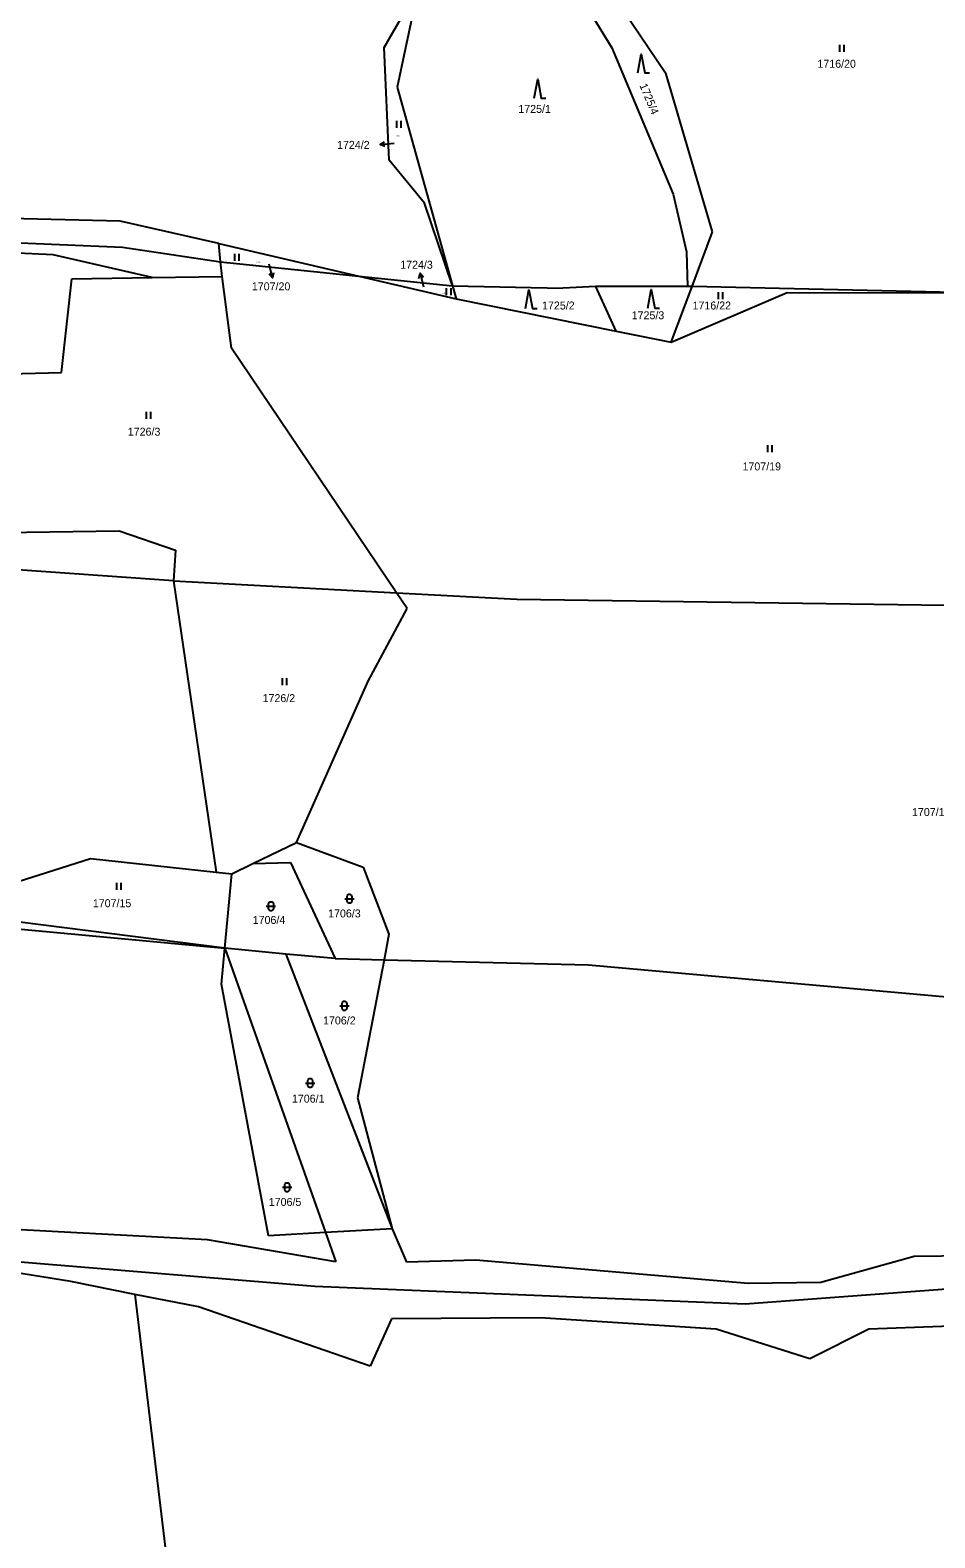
# Model space of a CAD drawing. Extents: x -609861 to -605046, y -1120287 to -1116307.
# Drawn here: x -608546.9 to -608353.7, y -1119519.3 to -1119197.4 of the extents above; entities that cross this region are included whole.
import ezdxf

# ---------------------------------------------------------------- set-up
doc = ezdxf.new("R2010")
doc.units = 0
for name, color, linetype in [('Vrstva 1', 7, 'Continuous'), ('Vrstva 2', 7, 'Continuous'), ('Vrstva 3', 7, 'Continuous'), ('Vrstva 7', 7, 'Continuous')]:
    doc.layers.add(name, color=color, linetype=linetype)

msp = doc.modelspace()

# ---------------------------------------------------------------- linework, layer by layer
at = {"layer": 'Vrstva 1'}
for p, q in [((-608446.56, -1119162.06), (-608422.64, -1119201.2)), ((-608411.09, -1119206.8), (-608441.64, -1119161.43)), ((-608471.27, -1119201.14), (-608463.96, -1119188.36)), ((-608463.96, -1119188.36), (-608468.52, -1119209.58)), ((-608470.2, -1119225.18), (-608471.27, -1119201.14)), ((-608422.64, -1119201.2), (-608409.54, -1119232.39)), ((-608401.21, -1119240.49), (-608411.09, -1119206.8)), ((-608468.52, -1119209.58), (-608456.66, -1119252)), ((-608462.69, -1119234.31), (-608470.2, -1119225.18)), ((-608409.54, -1119232.39), (-608406.75, -1119244.71)), ((-608527.65, -1119238.15), (-608582.05, -1119236.84)), ((-608456.66, -1119252), (-608462.69, -1119234.31)), ((-608617.51, -1119239.98), (-608527.15, -1119243.75)), ((-608506.57, -1119242.93), (-608527.65, -1119238.15)), ((-608506.18, -1119246.86), (-608506.57, -1119242.93)), ((-608506.57, -1119242.93), (-608476.7, -1119249.92)), ((-608405.54, -1119252.11), (-608401.21, -1119240.49)), ((-608541.93, -1119245.35), (-608572.44, -1119243.93)), ((-608520.83, -1119250.21), (-608541.93, -1119245.35)), ((-608527.15, -1119243.75), (-608506.18, -1119246.86)), ((-608406.75, -1119244.71), (-608406.51, -1119252.09)), ((-608520.83, -1119250.21), (-608505.87, -1119249.96)), ((-608506.18, -1119246.86), (-608476.7, -1119249.92)), ((-608505.87, -1119249.96), (-608506.18, -1119246.86)), ((-608503.85, -1119265.31), (-608505.87, -1119249.96)), ((-608476.7, -1119249.92), (-608456.66, -1119252)), ((-608476.7, -1119249.92), (-608455.88, -1119254.79)), ((-608540.17, -1119270.5), (-608537.92, -1119250.49)), ((-608537.92, -1119250.49), (-608520.83, -1119250.21)), ((-608456.66, -1119252), (-608433.13, -1119252.5)), ((-608456.66, -1119252), (-608455.88, -1119254.79)), ((-608426.05, -1119252.09), (-608433.13, -1119252.5)), ((-608421.77, -1119261.66), (-608426.05, -1119252.09)), ((-608406.51, -1119252.09), (-608426.05, -1119252.09)), ((-608409.97, -1119264.03), (-608405.54, -1119252.11)), ((-608405.54, -1119252.11), (-608406.51, -1119252.09)), ((-608344.74, -1119253.49), (-608405.54, -1119252.11)), ((-608455.88, -1119254.79), (-608421.77, -1119261.66)), ((-608409.97, -1119264.03), (-608385.2, -1119253.4)), ((-608385.2, -1119253.4), (-608344.74, -1119253.49)), ((-608421.77, -1119261.66), (-608409.97, -1119264.03)), ((-608468.64, -1119317.52), (-608503.85, -1119265.31)), ((-608581.1, -1119271.58), (-608540.17, -1119270.5)), ((-608552.52, -1119304.65), (-608527.83, -1119304.25)), ((-608527.83, -1119304.25), (-608515.81, -1119308.42)), ((-608515.81, -1119308.42), (-608516.24, -1119314.98)), ((-608516.24, -1119314.98), (-608552.52, -1119312.4)), ((-608516.24, -1119314.98), (-608507.13, -1119377.13)), ((-608516.24, -1119314.98), (-608468.64, -1119317.52)), ((-608468.64, -1119317.52), (-608442.96, -1119318.89)), ((-608466.37, -1119320.89), (-608468.64, -1119317.52)), ((-608442.96, -1119318.89), (-608343.15, -1119320.28)), ((-608474.7, -1119336.37), (-608466.37, -1119320.89)), ((-608490, -1119370.8), (-608474.7, -1119336.37)), ((-608499.3, -1119375.29), (-608490, -1119370.8)), ((-608490, -1119370.8), (-608475.76, -1119376.11)), ((-608569.78, -1119385.59), (-608533.97, -1119374.25)), ((-608533.97, -1119374.25), (-608507.13, -1119377.13)), ((-608503.82, -1119377.48), (-608499.3, -1119375.29)), ((-608499.3, -1119375.29), (-608491.26, -1119375.06)), ((-608491.26, -1119375.06), (-608481.74, -1119395.58)), ((-608507.13, -1119377.13), (-608503.82, -1119377.48)), ((-608505.31, -1119393.4), (-608503.82, -1119377.48)), ((-608475.76, -1119376.11), (-608470.26, -1119390.41)), ((-608560.52, -1119388.2), (-608505.31, -1119393.4)), ((-608505.31, -1119393.4), (-608560.31, -1119386.41)), ((-608470.26, -1119390.41), (-608471.3, -1119395.84)), ((-608506.03, -1119401.04), (-608505.31, -1119393.4)), ((-608492.26, -1119394.63), (-608505.31, -1119393.4)), ((-608505.31, -1119393.4), (-608483.78, -1119454.09)), ((-608481.74, -1119395.58), (-608492.26, -1119394.63)), ((-608492.26, -1119394.63), (-608469.59, -1119453.3)), ((-608481.74, -1119395.58), (-608471.3, -1119395.84)), ((-608471.3, -1119395.84), (-608476.95, -1119425.35)), ((-608471.3, -1119395.84), (-608427.62, -1119396.94)), ((-608427.62, -1119396.94), (-608309.88, -1119407.44)), ((-608496, -1119454.78), (-608506.03, -1119401.04)), ((-608476.95, -1119425.35), (-608469.59, -1119453.3)), ((-608509, -1119455.62), (-608571.9, -1119452.25)), ((-608481.57, -1119460.32), (-608509, -1119455.62)), ((-608483.78, -1119454.09), (-608496, -1119454.78)), ((-608469.59, -1119453.3), (-608483.78, -1119454.09)), ((-608483.78, -1119454.09), (-608481.57, -1119460.32)), ((-608469.59, -1119453.3), (-608466.51, -1119460.39)), ((-608578.72, -1119457.82), (-608486.04, -1119465.56)), ((-608358.11, -1119459.2), (-608378.07, -1119464.76)), ((-608248.43, -1119458.01), (-608358.11, -1119459.2)), ((-608538.2, -1119464.56), (-608559.23, -1119461.19)), ((-608451.69, -1119460), (-608466.51, -1119460.39)), ((-608393.53, -1119464.96), (-608451.69, -1119460)), ((-608524.5, -1119467.29), (-608538.2, -1119464.56)), ((-608486.04, -1119465.56), (-608394.17, -1119469.33)), ((-608394.17, -1119469.33), (-608328.49, -1119464.37)), ((-608378.07, -1119464.76), (-608393.53, -1119464.96)), ((-608510.94, -1119469.93), (-608524.5, -1119467.29)), ((-608524.5, -1119467.29), (-608508.41, -1119601.67)), ((-608474.23, -1119482.64), (-608510.94, -1119469.93)), ((-608469.73, -1119472.51), (-608474.23, -1119482.64)), ((-608437.96, -1119472.31), (-608469.73, -1119472.51)), ((-608400.4, -1119474.7), (-608437.96, -1119472.31)), ((-608380.43, -1119481.05), (-608400.4, -1119474.7)), ((-608367.77, -1119474.7), (-608380.43, -1119481.05)), ((-608325.7, -1119473.11), (-608367.77, -1119474.7))]:
    msp.add_line(p, q, dxfattribs=at)
at = {"layer": 'Vrstva 3'}
for p, q in [((-608374.08, -1119200.51), (-608374.08, -1119202.01)), ((-608373.08, -1119202.01), (-608373.08, -1119200.51)), ((-608468.64, -1119216.78), (-608468.64, -1119218.28)), ((-608467.64, -1119218.28), (-608467.64, -1119216.78)), ((-608503.24, -1119245.15), (-608503.24, -1119246.65)), ((-608502.24, -1119246.65), (-608502.24, -1119245.15)), ((-608458, -1119252.45), (-608458, -1119253.95)), ((-608457, -1119253.95), (-608457, -1119252.45)), ((-608399.94, -1119253.31), (-608399.94, -1119254.81)), ((-608398.94, -1119254.81), (-608398.94, -1119253.31)), ((-608522.1, -1119278.87), (-608522.1, -1119280.37)), ((-608521.1, -1119280.37), (-608521.1, -1119278.87)), ((-608389.41, -1119286.01), (-608389.41, -1119287.51)), ((-608388.41, -1119287.51), (-608388.41, -1119286.01)), ((-608493.02, -1119335.75), (-608493.02, -1119337.25)), ((-608492.02, -1119337.25), (-608492.02, -1119335.75)), ((-608528.42, -1119379.43), (-608528.42, -1119380.93)), ((-608527.42, -1119380.93), (-608527.42, -1119379.43))]:
    msp.add_line(p, q, dxfattribs=at)
for points in [[(-608417.14, -1119206.51), (-608416.39, -1119202.51), (-608415.64, -1119206.51), (-608414.64, -1119206.51)], [(-608439.24, -1119211.89), (-608438.49, -1119207.89), (-608437.74, -1119211.89), (-608436.74, -1119211.89)], [(-608441.13, -1119256.82), (-608440.38, -1119252.82), (-608439.63, -1119256.82), (-608438.63, -1119256.82)], [(-608415.01, -1119256.75), (-608414.26, -1119252.75), (-608413.51, -1119256.75), (-608412.51, -1119256.75)], [(-608496.44, -1119384.42), (-608495.17, -1119384.42), (-608494.44, -1119384.42)], [(-608479.7, -1119382.83), (-608478.43, -1119382.83), (-608477.7, -1119382.83)], [(-608480.77, -1119405.68), (-608479.5, -1119405.68), (-608478.77, -1119405.68)], [(-608488.07, -1119422.17), (-608486.8, -1119422.17), (-608486.07, -1119422.17)], [(-608493.01, -1119444.42), (-608491.74, -1119444.42), (-608491.01, -1119444.42)]]:
    msp.add_lwpolyline(points, dxfattribs=at)
for points in [[(-608479.2, -1119382.33), (-608479.1, -1119382.04), (-608478.85, -1119381.86), (-608478.54, -1119381.86), (-608478.29, -1119382.04), (-608478.19, -1119382.33), (-608478.19, -1119383.33), (-608478.29, -1119383.62), (-608478.54, -1119383.8), (-608478.85, -1119383.8), (-608479.1, -1119383.62), (-608479.2, -1119383.33)], [(-608495.94, -1119383.92), (-608495.84, -1119383.63), (-608495.59, -1119383.45), (-608495.28, -1119383.45), (-608495.03, -1119383.63), (-608494.93, -1119383.92), (-608494.93, -1119384.92), (-608495.03, -1119385.21), (-608495.28, -1119385.39), (-608495.59, -1119385.39), (-608495.84, -1119385.21), (-608495.94, -1119384.92)], [(-608480.27, -1119405.18), (-608480.17, -1119404.89), (-608479.92, -1119404.71), (-608479.61, -1119404.71), (-608479.36, -1119404.89), (-608479.26, -1119405.18), (-608479.26, -1119406.18), (-608479.36, -1119406.47), (-608479.61, -1119406.65), (-608479.92, -1119406.65), (-608480.17, -1119406.47), (-608480.27, -1119406.18)], [(-608487.57, -1119421.67), (-608487.47, -1119421.38), (-608487.22, -1119421.2), (-608486.91, -1119421.2), (-608486.66, -1119421.38), (-608486.56, -1119421.67), (-608486.56, -1119422.67), (-608486.66, -1119422.96), (-608486.91, -1119423.14), (-608487.22, -1119423.14), (-608487.47, -1119422.96), (-608487.57, -1119422.67)], [(-608492.51, -1119443.92), (-608492.41, -1119443.63), (-608492.16, -1119443.45), (-608491.85, -1119443.45), (-608491.6, -1119443.63), (-608491.5, -1119443.92), (-608491.5, -1119444.92), (-608491.6, -1119445.21), (-608491.85, -1119445.39), (-608492.16, -1119445.39), (-608492.41, -1119445.21), (-608492.51, -1119444.92)]]:
    msp.add_lwpolyline(points, close=True, dxfattribs=at)
at = {"layer": 'Vrstva 7'}
for p, q in [((-608472.138, -1119221.794), (-608469.15, -1119221.53)), ((-608495.134, -1119250.273), (-608495.81, -1119247.35)), ((-608463.608, -1119249.305), (-608462.86, -1119252.21))]:
    msp.add_line(p, q, dxfattribs=at)
for points in [[(-608471.098, -1119222.204), (-608472.138, -1119221.794), (-608471.186, -1119221.208)], [(-608494.872, -1119249.186), (-608495.134, -1119250.273), (-608495.846, -1119249.411)], [(-608463.843, -1119250.398), (-608463.608, -1119249.305), (-608462.874, -1119250.148)]]:
    msp.add_lwpolyline(points, dxfattribs=at)

# ---------------------------------------------------------------- texts
at = {"layer": 'Vrstva 2'}
for s, height, p in [('1716/20', 1.7, (-608378.777, -1119205.43)), ('1725/1', 1.7, (-608442.627, -1119215.06)), ('1724/2', 0.2, (-608468.714, -1119220.09)), ('1707/20', 0.2, (-608498.604, -1119247.03)), ('1724/3', 0.2, (-608458.884, -1119253.63)), ('1725/2', 1.7, (-608437.567, -1119257.03)), ('1716/22', 1.7, (-608405.437, -1119257.03)), ('1725/3', 1.7, (-608418.427, -1119259.12)), ('1726/3', 1.7, (-608526.007, -1119283.97)), ('1707/19', 1.7, (-608394.767, -1119291.38)), ('1726/2', 1.7, (-608497.227, -1119340.85)), ('1707/18', 1.7, (-608358.587, -1119365.17)), ('1707/15', 1.7, (-608533.467, -1119384.63)), ('1706/3', 1.7, (-608483.237, -1119386.81)), ('1706/4', 1.7, (-608499.337, -1119388.2)), ('1706/2', 1.7, (-608484.317, -1119409.66)), ('1706/1', 1.7, (-608490.967, -1119426.35)), ('1706/5', 1.7, (-608495.907, -1119448.4))]:
    msp.add_text(s, height=height, dxfattribs=at).set_placement(p)
msp.add_text('1725/4', height=1.7, rotation=292.49496, dxfattribs=at).set_placement((-608416.8, -1119209.183))
at = {"layer": 'Vrstva 7'}
for s, p in [('1724/2', (-608481.331, -1119222.74)), ('1724/3', (-608467.845, -1119248.33)), ('1707/20', (-608499.521, -1119252.95))]:
    msp.add_text(s, height=1.7, dxfattribs=at).set_placement(p)

doc.saveas('drawing.dxf')
